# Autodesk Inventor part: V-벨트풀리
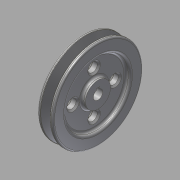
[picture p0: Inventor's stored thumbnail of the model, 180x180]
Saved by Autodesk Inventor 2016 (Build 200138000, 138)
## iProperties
Created: 2015-09
Part Number: V-벨트풀리
Material: 강철, 연강
Document SubType Name: Modeling
Designer: mduedu
Density: 1 g/cm^3
Appearance: 강철
Author: mduedu
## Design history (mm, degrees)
sketch "스케치1"
  geometry: L1 (-10, 0)-(10, 0); L2 (-10, 0)-(-10, 57.5); L3 (-10, 57.5)-(-6.062, 57.5); L4 (-6.062, 57.5)-(-2.001, 45); L5 (-2.001, 45)-(2.001, 45); L6 (2.001, 45)-(6.062, 57.5); L7 (6.062, 57.5)-(10, 57.5); L8 (10, 57.5)-(10, 0); L9 (0, 0)-(0, 45); L10 (-10, 53)-(10, 53); 3 further points
  constraints: 20 end point, 6 point on line, 3 perpendicular, 2 midpoint, 2 parallel, 2 symmetric about line, 1 coincident, 1 collinear, 1 equal length, 1 horizontal, 1 vertical, 1 vertical alignment
  dimensions: "d0" = 20 distance between parallel lines of L8 L2; "d2" = 115 diameter of L3 L1; "d5" = 8 distance between parallel lines of L5 L10; "d6" = 9.2 distance of point (4.6, 53) point (-4.6, 53); "d7" = 36 deg angle of L6 L4; "d40" = 4.5 distance between parallel lines of L10 L3
revolve "회전1" sketch "스케치1" stored, may be unused: angle "d8" = 90 deg
sketch "스케치2"
  geometry: C1 r 16 at (0, 0); C2 r 41 at (0, 0); 1 further point
  constraints: 2 centre point, 2 coincident
  dimensions: "d9" = 32 diameter of C1; "d41" = 82 diameter of C2
extrude "돌출5" cut sketch "스케치2" distance "d42" = 5; taper "d43" = 0 deg
hole "구멍2" diameter "d46" = 12; stored, may be unused: countersink angle "d50" = 90 deg, drill point angle "d52" = 118 deg; dims "d44" = 10, "d45" = 10, "d47" = 6, "d48" = 4, "d49" = 2, "d51" = 8
sketch "스케치8"
  geometry: L1 (-2, 5.657)-(2, 5.657); L2 (2, 5.657)-(2, 7.8); L3 (2, 7.8)-(-2, 7.8); L4 (-2, 7.8)-(-2, 5.657); A1 r 6 centre (0, 0) between (-2, 5.657) and (2, 5.657) reference; 1 further point
  constraints: 8 end point, 2 parallel, 2 point on circle, 1 horizontal, 1 perpendicular
  dimensions: "d53" = 4 distance of L2.end L3.end; "d55" = 13.8 dimension on A1 L3
extrude "돌출6" cut sketch "스케치8" stored distance "d56" = 5; taper "d57" = 0 deg
sketch "스케치9"
  geometry: C1 r 6 at (0, 27); 1 further point
  constraints: 1 centre point, 1 vertical alignment
  dimensions: "d61" = 12 diameter of C1; "d62" = 27 distance of C1.centre point (0, 0)
extrude "돌출7" cut sketch "스케치9" stored distance "d63" = 5; taper "d64" = 0 deg
chamfer "모따기3" distance "d65" = 2; stored, may be unused: second distance "d66" = 2, angle "d67" = 45 deg
fillet "모깎기5" dims "d71" = 2, "d72" = 1, "d73" = 0.5
fillet "모깎기6" dims "d74" = 3
fillet "모깎기7" dims "d75" = 3
fillet "모깎기8" dims "d76" = 3
sketch "스케치10"
  geometry: C1 r 47.5 at (0, 0); 1 further point
  constraints: 1 centre point, 1 coincident, 1 other
  dimensions: "d77" = 95 diameter of C1
extrude "돌출8" join sketch "스케치10" distance "d80" = 0.5; taper "d81" = 0 deg
node "솔리드1"
mirror "대칭2"
pattern_circular "원형 패턴1" dims "d69" = 360 deg
